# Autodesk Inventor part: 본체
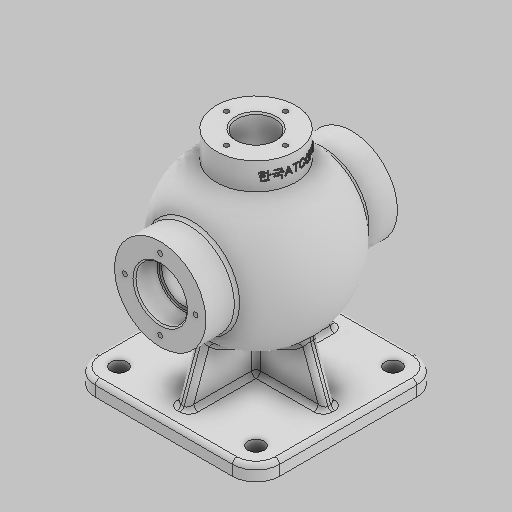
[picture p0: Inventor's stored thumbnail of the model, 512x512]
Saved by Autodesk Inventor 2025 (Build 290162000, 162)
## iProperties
Created: 2024-07
Part Number: 본체
Material: 일반
Document SubType Name: Modeling
Designer: 현기
Density: 1 g/cm^3
Appearance: 기본값
Author: 현기
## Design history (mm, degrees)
sketch "스케치1"
  geometry: L1 (-62.5, 62.5)-(62.5, 62.5); L2 (62.5, 62.5)-(62.5, -62.5); L3 (62.5, -62.5)-(-62.5, -62.5); L4 (-62.5, -62.5)-(-62.5, 62.5); L5 (-62.5, 62.5)-(62.5, -62.5); L6 (62.5, 62.5)-(-62.5, -62.5); 1 further point
  constraints: 12 end point, 2 midpoint, 2 parallel, 1 horizontal, 1 perpendicular
  dimensions: "d0" = 125 distance of L2.end L3.end; "d1" = 125 distance of L1.end L2.end
extrude "돌출1" new body sketch "스케치1" distance "d2" = 10; taper "d3" = 0 deg
sketch "스케치2"
  geometry: L1 (0, 0)-(0, 85); L2 (0, 149.344)-(0, 26.445); A1 r 44 centre (0, 85) between (0, 41) and (0, 129); A2 r 54 centre (0, 85) between (0, 31) and (0, 139)
  constraints: 5 point on line, 4 end point, 4 point on circle, 2 centre point, 2 coincident, 1 vertical
  dimensions: "d4" = 85 distance of L1.start L1.end; "d6" = 44 radius of A1; "d7" = 54 radius of A2
revolve "회전1" sketch "스케치2" stored, may be unused: angle "d8" = 90 deg
node "작업 평면1"
sketch "스케치3"
  geometry: C1 r 31 at (0, 85); 1 further point
  constraints: 1 centre point
  dimensions: "d10" = 62 diameter of C1
extrude "돌출2" join sketch "스케치3" stored distance "d11" = 130; taper "d12" = 0 deg
node "작업 평면2"
sketch "스케치4"
  geometry: C1 r 27 at (0, 0); 1 further point
  constraints: 1 centre point, 1 coincident
  dimensions: "d14" = 54 diameter of C1
extrude "돌출3" join sketch "스케치4" stored distance "d15" = 10; taper "d16" = 0 deg
sketch "스케치5"
  geometry: L1 (-62.5, 10)-(62.5, 10) reference; L2 (-62.5, 10)-(-50.5, 10); L3 (-50.5, 10)-(-36.565, 48.286); L4 (-62.5, 0)-(-62.5, 10) reference; L5 (-50.5, 10)-(0, 10); L6 (0, 10)-(0, 34.977); L7 (0, 34.977)-(-36.565, 48.286); 1 further point
  constraints: 10 end point, 2 point on line, 1 midpoint, 1 vertical
  dimensions: "d17" = 12 distance of L1.start L2.end; "d18" = 20 deg angle of L3 L4
extrude "돌출4" join sketch "스케치5" stored distance "d19" = 8; taper "d20" = 0 deg
fillet "모깎기1" dims "d28" = 16
fillet "모깎기2" dims "d29" = 3
fillet "모깎기3" dims "d30" = 3
fillet "모깎기4" dims "d31" = 3
fillet "모깎기5" dims "d32" = 3
sketch "스케치6"
  geometry: C1 r 31 at (0, 0) reference; 2 further points
  constraints: 1 coincident
hole "구멍1" sketch "스케치6" at (0, 0) diameter "d33" = 30; stored, may be unused: countersink angle "d37" = 90 deg, drill point angle "d39" = 0 deg; dims "d34" = 11, "d35" = 35, "d36" = 16, "d38" = 50
sketch "스케치7"
  geometry: C1 r 31 at (0, 0) reference; 2 further points
  constraints: 1 coincident
hole "구멍2" sketch "스케치7" at (0, 0) diameter "d40" = 30; stored, may be unused: countersink angle "d44" = 90 deg, drill point angle "d46" = 0 deg; dims "d41" = 6, "d42" = 35, "d43" = 16, "d45" = 50
fillet "모깎기6" dims "d47" = 0.6
sketch "스케치8"
  geometry: C1 r 27 at (0, 0) reference; 2 further points
  constraints: 1 coincident
hole "구멍3" sketch "스케치8" at (0, 0) diameter "d48" = 26; stored, may be unused: countersink angle "d52" = 90 deg, drill point angle "d54" = 0 deg; dims "d49" = 6, "d50" = 35, "d51" = 16, "d53" = 50
chamfer "모따기1" distance "d55" = 1; stored, may be unused: second distance "d56" = 2, angle "d57" = 45 deg
sketch "스케치9" dims "d58" = 48
  geometry: L1 (0, 49.505)-(0, -35.875); L2 (-27, 46.765)-(27, 46.765) reference; 3 further points
  constraints: 2 end point, 1 perpendicular, 1 point on line, 1 vertical alignment, 2 other
hole "구멍4" sketch "스케치9" at (0, 24) diameter "d59" = 3.242; stored, may be unused: countersink angle "d63" = 90 deg, drill point angle "d65" = 120 deg; dims "d60" = 12, "d61" = 4, "d62" = 2, "d64" = 15
sketch "스케치10" dims "d69" = 40
  geometry: L1 (0, 33.22)-(0, -33.562); C1 r 13 at (0, 0) reference; 3 further points
  constraints: 2 end point, 1 coincident, 1 point on line, 1 vertical, 1 vertical alignment, 2 other
hole "구멍5" sketch "스케치10" at (0, 20) diameter "d70" = 3.242; stored, may be unused: countersink angle "d74" = 90 deg, drill point angle "d76" = 120 deg; dims "d71" = 9, "d72" = 4, "d73" = 2, "d75" = 11
sketch "스케치11"
  geometry: A1 r 16 centre (-46.5, 46.5) between (-46.5, 62.5) and (-62.5, 46.5) reference; A2 r 16 centre (46.5, 46.5) between (62.5, 46.5) and (46.5, 62.5) reference; A3 r 16 centre (46.5, -46.5) between (46.5, -62.5) and (62.5, -46.5) reference; A4 r 16 centre (-46.5, -46.5) between (-62.5, -46.5) and (-46.5, -62.5) reference; 5 further points
  constraints: 4 coincident
hole "구멍6" sketch "스케치11" at (-46.5, 46.5), (46.5, 46.5), (46.5, -46.5), (-46.5, -46.5) diameter "d80" = 11; stored, may be unused: countersink angle "d84" = 90 deg, drill point angle "d86" = 120 deg; dims "d81" = 9, "d82" = 4, "d83" = 2, "d85" = 11
node "작업 평면3"
sketch "스케치12"
  geometry: L1 (0, 46.5)-(0, -46.5) reference; L2 (150, -27)-(150, 27) reference; 3 further points
  constraints: 1 horizontal alignment, 1 midpoint, 1 other
  dimensions: "d88" = 9 distance from line of L2 point (141, 0)
feature "엠보싱1" sketch "스케치12" dims "d0" = 125, "d1" = 125, "d11" = 130, "d12" = 0, "d89" = 0.5, "d90" = 0
feature "Ʈ耀ư耀Ʋ耀ƴ耀ƶ耀Ƹ耀ƺ耀Ƽ耀" dims "d0" = 125, "d1" = 125, "d2" = 10, "d3" = 0, "d4" = 85, "d6" = 44, "d7" = 54, "d8" = 90 deg, "d9" = 65, "d10" = 62, "d11" = 130, "d12" = 0, "d13" = 150, "d14" = 54, "d15" = 10, "d16" = 0, "d17" = 12, "d18" = 20 deg, "d19" = 8, "d20" = 0, "d21" = 0.5, "d22" = 2, "d23" = 0, "d24" = 20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
node "솔리드1"
mirror "미러1"
pattern_circular "원형 패턴1" dims angle "d26" = 360 deg
pattern_circular "원형 패턴2" dims angle "d67" = 360 deg
mirror "미러2"
pattern_circular "원형 패턴3" dims angle "d78" = 360 deg
feature "A9D066F2-1C7D-4E18-AEED-F7BC21143FA4" dims "d33" = 30, "d34" = 11, "d35" = 35, "d36" = 16, "d37" = 90 deg, "d38" = 50, "d39" = 0
